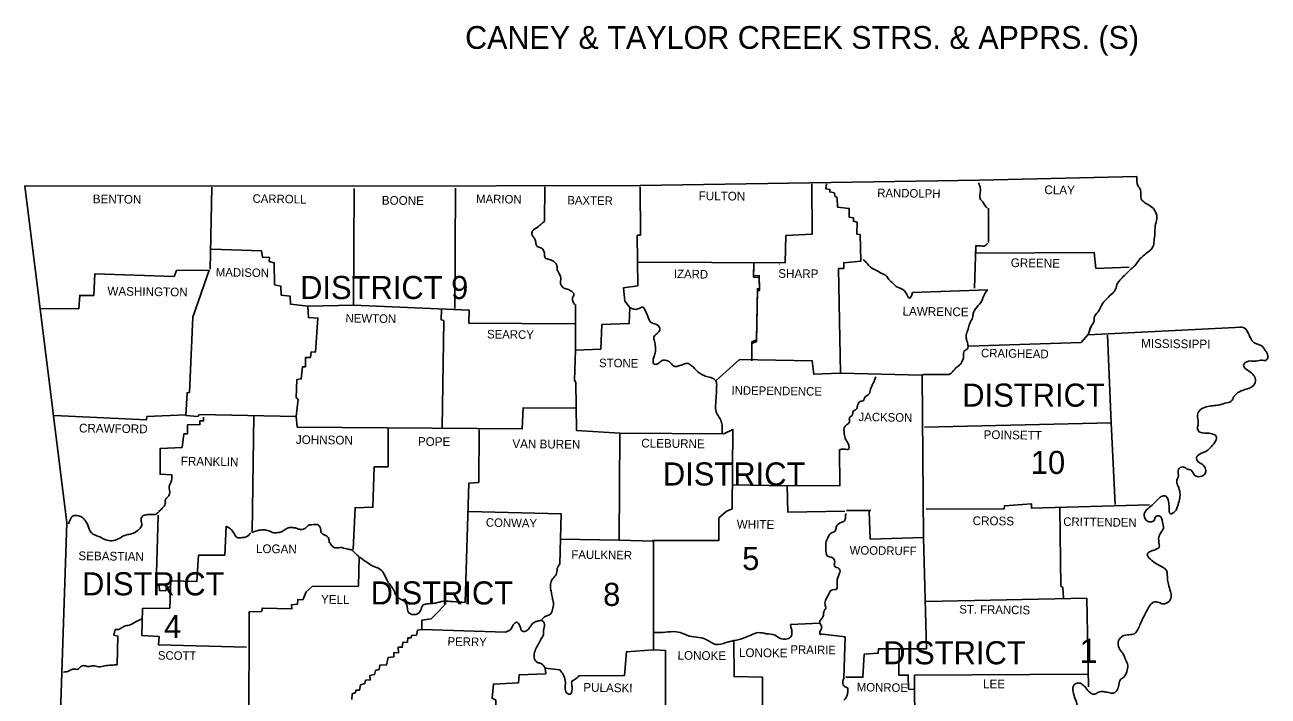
# Model space of a CAD drawing. Extents: x 172 to 3385, y 73 to 2074.
# Drawn here: x 2704 to 3304, y 1710 to 2034 of the extents above; entities that cross this region are included whole.
import ezdxf

# ---------------------------------------------------------------- set-up
doc = ezdxf.new("R2010")
doc.units = 0
for name, color, linetype in [('R_Border', 7, 'Continuous'), ('R_Border Prem', 7, 'Continuous'), ('R_Grid', 7, 'Continuous')]:
    doc.layers.add(name, color=color, linetype=linetype)

msp = doc.modelspace()

# ---------------------------------------------------------------- linework, layer by layer
at = {"layer": 'R_Border Prem'}
for p, q in [((3216.98, 1884.51), (3218.15, 1888.13)), ((3217.27, 1885.68), (3218.45, 1888.52)), ((3100.35, 1799.78), (3112, 1799.78))]:
    msp.add_line(p, q, dxfattribs=at)
for points in [[(2703.71, 1956.42), (2861.92, 1956.32), (3000.75, 1956.61), (3164.54, 1959.16), (3240.46, 1960.92)], [(3083.62, 1957.49), (3083.82, 1933.23), (3071.1, 1932.55), (3070.71, 1919.24), (2999.97, 1919.63)], [(3090.67, 1957.4), (3090.37, 1955.05), (3092.33, 1954.76), (3092.23, 1953.58), (3094.48, 1953.09), (3094.68, 1951.53), (3095.75, 1950.84), (3096.05, 1946.15), (3101.63, 1945.56), (3101.63, 1941.35), (3103.68, 1941.06), (3103.68, 1939.39), (3105.44, 1938.9), (3105.34, 1933.23), (3106.91, 1932.94), (3107.3, 1920.12), (3098.98, 1919.34), (3099.08, 1916.6), (3096.54, 1916.5), (3097.42, 1866.01), (3136.85, 1865.13), (3137.53, 1786.66), (3111.8, 1785.98), (3111.31, 1799.19)], [(2703.71, 1956.42), (2723.96, 1793.81), (2715.15, 1528.37)], [(2794.01, 1955.83), (2793.13, 1916.21)], [(2793.82, 1925.89), (2817.89, 1925.11), (2818.47, 1921.98), (2821.8, 1921.88), (2821.7, 1919.92), (2824.05, 1919.34), (2824.25, 1908.67), (2827.28, 1907.99), (2827.48, 1903.78), (2831.78, 1903.19), (2831.98, 1899.28), (2840.49, 1898.4), (2862.4, 1898.89), (2862.6, 1955.15)], [(2911.62, 1955.34), (2911.33, 1897.22)], [(2954.67, 1956.03), (2954.47, 1939.3)], [(3000.75, 1956.03), (3000.95, 1932.74), (2999.28, 1932.64), (2999.58, 1908.28), (2992.73, 1907.3), (2993.32, 1900.75), (2995.66, 1897.71), (2995.47, 1889.98), (2982.16, 1889.5), (2981.67, 1877.56), (2969.54, 1877.17), (2968.95, 1862.69), (2969.64, 1861.51), (2969.93, 1838.42), (2990.87, 1837.05), (2990.58, 1785.49), (3007.21, 1785), (3007.21, 1732.56), (2994.1, 1731.58), (2993.12, 1720.04), (2971.11, 1719.94)], [(3168.84, 1945.66), (3168.84, 1929.12)], [(3162.19, 1907.11), (3162.68, 1927.56), (3162.68, 1923.94), (3219.91, 1924.23), (3220.7, 1916.6), (3236.84, 1917.18)], [(2711.44, 1897.22), (2729.73, 1897.13), (2730.22, 1903.58), (2736.97, 1903.58), (2737.56, 1914.05), (2775.72, 1912.68), (2776.89, 1915.62), (2792.64, 1915.72), (2784.72, 1893.02), (2783.15, 1856.72), (2781.98, 1856.62), (2781.39, 1845.66), (2787.17, 1845.17), (2788.05, 1846.05), (2834.72, 1845.17), (2835.21, 1839.99)], [(3055.64, 1918.95), (3055.44, 1913.27), (3058.18, 1913.07), (3058.28, 1906.81), (3057.3, 1906.81), (3056.91, 1882.16), (3054.66, 1881.18), (3054.66, 1872.96)], [(3055.64, 1918.06), (3055.44, 1912.39), (3058.18, 1912.19), (3058.28, 1905.93), (3057.3, 1905.93), (3056.91, 1881.28), (3054.66, 1880.3), (3054.66, 1872.08)], [(3067.87, 1918.75), (3067.97, 1918.85)], [(3132.25, 1904.95), (3168.55, 1906.23)], [(2840.29, 1898.2), (2840.68, 1892.92), (2845.18, 1892.63), (2844.01, 1876.19), (2841.96, 1876.29), (2841.56, 1873.65), (2839.22, 1873.65), (2839.12, 1869.14), (2837.65, 1869.05), (2837.16, 1863.27), (2835.01, 1862.98), (2834.72, 1854.17), (2835.69, 1853.49), (2834.72, 1845.17)], [(2862.4, 1898.89), (2918.17, 1896.54), (2918.08, 1890.18), (2969.25, 1889.79)], [(2904.77, 1896.83), (2904.67, 1891.75), (2905.94, 1891.45), (2905.16, 1839.79)], [(2969.54, 1877.17), (2969.44, 1899.18)], [(3159.25, 1879.12), (3213.55, 1880.89), (3216.78, 1884.6)], [(3216.98, 1884.51), (3291.24, 1888.32)], [(3226.37, 1884.41), (3228.04, 1842.04), (3229.99, 1802.61)], [(3037.44, 1862.49), (3048.6, 1872.57), (3083.82, 1872.08), (3084.5, 1865.52), (3097.32, 1866.01)], [(3149.67, 1865.33), (3137.73, 1865.33), (3136.85, 1865.13)], [(2835.21, 1839.99), (2943.81, 1839.11), (2944.3, 1849.38), (2969.54, 1849.09)], [(2969.25, 1849.19), (2969.54, 1849.48)], [(2717.89, 1845.56), (2762.41, 1843.51), (2762.61, 1845.08), (2781.2, 1845.96)], [(2790, 1844.78), (2790, 1843.02), (2788.14, 1843.02), (2788.24, 1841.26), (2782.27, 1841.16), (2782.18, 1836.76), (2780.51, 1836.76), (2779.63, 1830.2), (2769.06, 1829.71), (2768.97, 1817.29), (2774.64, 1816.9)], [(2814.17, 1845.56), (2813.48, 1789.11)], [(2879.14, 1839.21), (2879.04, 1820.91), (2872.29, 1820.81), (2871.7, 1801.34), (2863.09, 1801.05), (2862.11, 1780.89)], [(2922.97, 1838.72), (2922.77, 1813.28), (2918.08, 1812.89), (2916.22, 1755.36)], [(2990.87, 1837.05), (3041.16, 1836.76), (3045.46, 1838.81), (3045.17, 1800.56), (3042.24, 1799.29), (3039.59, 1797.04), (3038.71, 1796.16), (3038.62, 1785.2), (3006.62, 1785.2)], [(3228.04, 1842.04), (3137.92, 1839.99)], [(3096.93, 1829.03), (3097.12, 1811.81), (3071.69, 1811.71), (3045.56, 1812.2)], [(3071.69, 1811.71), (3072.08, 1798.89), (3099.57, 1799.38)], [(3138.71, 1800.36), (3176.47, 1800.56), (3176.57, 1801.93), (3189.68, 1802.91), (3189.68, 1800.85), (3246.63, 1802.42)], [(3203.38, 1800.85), (3203.87, 1763.18), (3204.75, 1762.6), (3205.04, 1757.51)], [(2767.99, 1797.53), (2767.01, 1763.87), (2768.48, 1763.48), (2768.77, 1761.13), (2771.71, 1760.93), (2772, 1762.6), (2774.35, 1762.99)], [(2917.88, 1799.29), (2962.59, 1798.21), (2962.01, 1774.04)], [(3100.35, 1798.11), (3099.86, 1798.01)], [(2800.86, 1792.24), (2800.18, 1778.25), (2787.46, 1778.15), (2786.77, 1765.43), (2774.15, 1765.73), (2773.76, 1752.62), (2760.55, 1752.52), (2760.16, 1739.41), (2768.48, 1738.92), (2768.18, 1734.91), (2810.65, 1733.73)], [(2962.1, 1785.88), (2990.58, 1785.49)], [(3137.53, 1786.66), (3139, 1733.05), (3115.71, 1732.95), (3115.62, 1730.8), (3108.87, 1730.41), (3108.28, 1719.25), (3100.06, 1719.25)], [(2865.14, 1777.27), (2864.75, 1763.18), (2842.45, 1763.09), (2839.51, 1760.54), (2837.85, 1756.63), (2835.4, 1756.82), (2835.3, 1754.57), (2832.47, 1754.28), (2832.56, 1752.22), (2818.38, 1752.62), (2817.89, 1751.05), (2812.02, 1750.86), (2811.82, 1693.62)], [(2907.12, 1754.96), (2903.6, 1751.15), (2899.78, 1747.53), (2895.38, 1746.84), (2895.38, 1742.25), (2893.22, 1741.95), (2892.83, 1739.6), (2890.39, 1739.41), (2890.19, 1738.33), (2888.53, 1738.23), (2888.43, 1736.18), (2886.08, 1736.08), (2885.89, 1733.73), (2883.93, 1733.73), (2884.03, 1730.99), (2881.88, 1731.19), (2881.78, 1729.04), (2879.14, 1728.84), (2878.35, 1725.32), (2875.03, 1725.03), (2874.73, 1723.07), (2872.97, 1722.58), (2872.48, 1720.52), (2870.23, 1720.04), (2870.43, 1717.98), (2868.18, 1717.78), (2867.79, 1716.22), (2865.73, 1715.63), (2865.24, 1712.99), (2863.68, 1713.09), (2863.19, 1711.72), (2861.72, 1711.23), (2861.62, 1708.59)], [(3138.71, 1755.85), (3216.39, 1757.41)], [(3216.39, 1757.41), (3217.18, 1714.56)], [(2748.32, 1725.22), (2748.62, 1739.02), (2746.66, 1739.6), (2747.25, 1742.25)], [(2935.79, 1741.07), (2895.47, 1742.34)], [(3073.25, 1744.69), (3087.44, 1745.38)], [(3045.86, 1737.06), (3046.05, 1719.55), (3059.85, 1719.25), (3059.95, 1681.68)], [(3087.44, 1740.29), (3099.67, 1738.72), (3098.98, 1718.76)], [(3007.21, 1732.56), (3012.88, 1732.17), (3012.98, 1694.79), (3007.89, 1673.56), (3018.75, 1673.07), (3018.66, 1655.07)], [(3125.69, 1732.46), (3125.6, 1720.33), (3130.1, 1720.33), (3130.29, 1713.58), (3133.13, 1713.28)], [(2961.91, 1722.77), (2954.86, 1723.56), (2955.16, 1720.92), (2942.34, 1720.43), (2941.95, 1716.61), (2929.91, 1715.93), (2929.23, 1709.08), (2930.99, 1708.2), (2930.99, 1703.7)], [(2992.63, 1720.13), (2993.12, 1720.62)], [(3138.71, 1633.54), (3146.34, 1634.03), (3146.24, 1653.9), (3139.1, 1654.38), (3139.49, 1693.23), (3133.33, 1694.11), (3133.13, 1720.23), (3216.59, 1720.82)]]:
    msp.add_lwpolyline(points, dxfattribs=at)
for points in [[(3164.05, 1957.89), (3164.93, 1955.44), (3164.83, 1952.8), (3164.83, 1950.35), (3166.1, 1948.69), (3167.37, 1946.63), (3168.35, 1945.75)], [(3240.46, 1960.92), (3240.95, 1956.61), (3242.32, 1954.36), (3242.52, 1950.25), (3244.18, 1948.49), (3247.02, 1946.73), (3249.56, 1943.89), (3250.15, 1940.57), (3249.36, 1937.14), (3249.17, 1933.33), (3248.78, 1930), (3248.19, 1926.97), (3245.84, 1924.52), (3243.59, 1922.76), (3241.54, 1920.71), (3240.07, 1918.55), (3237.53, 1916.21), (3234.98, 1913.76), (3232.93, 1911.61), (3230.87, 1908.87), (3229.89, 1905.83), (3227.64, 1903.68), (3225.88, 1901.73), (3223.53, 1899.08), (3222.36, 1896.44), (3220.11, 1893.41), (3219.62, 1890.47), (3218.15, 1888.13), (3218.06, 1887.73)], [(2954.47, 1939.3), (2952.71, 1937.83), (2951.15, 1936.46), (2948.8, 1934.8), (2948.5, 1933.23), (2949.29, 1931.66), (2950.07, 1930.39), (2950.36, 1928.63), (2951.05, 1927.16), (2952.71, 1926.58), (2954.08, 1925.31), (2954.57, 1923.54), (2954.77, 1921.88), (2956.33, 1921.1), (2958.09, 1920.51), (2959.76, 1919.34), (2960.54, 1917.87), (2960.73, 1916.01), (2961.42, 1914.54), (2962.2, 1912.78), (2962.4, 1911.31), (2962.2, 1909.85), (2962.59, 1908.48), (2963.87, 1907.11), (2966.12, 1906.42), (2967.68, 1905.44), (2968.76, 1904.07), (2968.07, 1902.41), (2968.17, 1900.94), (2969.05, 1899.18)], [(3168.45, 1928.83), (3167.18, 1927.56), (3164.73, 1927.56), (3162.68, 1927.56)], [(3108.38, 1921), (3110.53, 1918.75), (3112.39, 1916.89), (3114.54, 1915.81), (3117.08, 1914.35), (3119.33, 1913.17), (3120.8, 1911.31), (3122.86, 1909.26), (3124.91, 1907.6), (3128.14, 1906.03), (3129.22, 1904.37), (3130.68, 1902.31), (3132.25, 1904.95)], [(3168.25, 1906.13), (3166.79, 1903.78), (3165.61, 1901.04), (3163.26, 1897.91), (3161.5, 1894.88), (3161.21, 1892.82), (3159.84, 1890.08), (3159.06, 1887.34), (3158.18, 1884.99), (3158.18, 1882.55), (3158.86, 1880.1), (3158.67, 1877.85), (3157.2, 1876.78), (3156.81, 1873.94), (3156.22, 1871.98), (3154.95, 1870.03), (3153.09, 1868.56), (3151.13, 1866.31), (3149.67, 1865.33)], [(2995.66, 1897.71), (2999.58, 1897.03), (3001.93, 1897.91), (3003.59, 1895.37), (3004.47, 1893.41), (3005.94, 1890.57), (3008.29, 1889.69), (3010.05, 1888.13), (3010.05, 1886.46), (3008.48, 1884.9), (3007.31, 1883.33), (3007.7, 1881.47), (3008.09, 1878.93), (3008.09, 1876.48), (3007.5, 1874.23), (3007.01, 1872.18), (3007.5, 1870.42), (3009.36, 1870.71), (3011.32, 1872.18), (3013.37, 1872.18), (3015.33, 1871.1), (3017.38, 1869.24), (3019.44, 1869.63), (3021.1, 1870.12), (3023.45, 1870.81), (3025.11, 1869.93), (3026.58, 1868.75), (3028.34, 1866.89), (3030.01, 1865.72), (3032.16, 1864.64), (3034.8, 1863.96), (3037.25, 1862.3), (3037.64, 1859.46), (3037.54, 1857.01), (3037.34, 1853.98), (3037.15, 1850.65), (3037.44, 1847.42), (3038.52, 1845.27), (3039.89, 1842.73), (3040.28, 1840.38), (3040.18, 1836.66)], [(3290.16, 1888.22), (3291.24, 1888.32), (3294.57, 1884.8), (3296.03, 1881.86), (3298.19, 1880.2), (3300.63, 1879.32), (3302.49, 1877.07), (3303.76, 1874.62), (3303.08, 1872.47), (3300.34, 1872.28), (3297.31, 1871.79), (3294.37, 1871.88), (3292.02, 1869.93), (3294.18, 1867.29), (3297.01, 1864.84), (3297.8, 1862.2), (3296.23, 1859.65), (3293.1, 1858.28), (3290.07, 1857.11), (3287.33, 1854.76), (3286.05, 1852.51), (3283.02, 1851.53), (3279.89, 1850.65), (3277.15, 1850.36), (3274.02, 1849.77), (3270.99, 1848.3), (3269.72, 1845.76), (3270.11, 1842.14), (3270.01, 1838.32), (3273.24, 1837.05), (3276.08, 1836.95), (3278.81, 1835.49), (3278.52, 1833.33), (3276.47, 1830.6), (3274.02, 1828.44), (3271.57, 1827.37), (3269.32, 1825.31), (3270.11, 1823.26), (3272.16, 1821.89), (3273.63, 1819.64), (3273.43, 1817.58), (3271.09, 1816.11), (3268.54, 1816.7), (3266.68, 1819.15), (3264.53, 1819.93), (3262.67, 1820.81), (3260.52, 1819.54), (3260.52, 1816.7), (3259.74, 1813.67), (3260.42, 1811.42), (3261.3, 1808.29), (3261.2, 1805.94), (3260.42, 1802.61), (3258.76, 1799.19), (3256.8, 1798.11), (3256.02, 1801.83), (3255.63, 1804.86), (3254.45, 1806.62), (3252.89, 1806.72), (3250.83, 1805.25), (3248.58, 1803), (3245.74, 1800.56), (3244.08, 1798.11), (3244.96, 1795.08), (3247.11, 1794.3), (3248.78, 1794.88), (3249.66, 1796.84), (3251.32, 1797.13), (3252.89, 1794.1)], [(3114.44, 1864.25), (3113.27, 1861.22), (3111.9, 1858.28), (3111.02, 1855.74), (3109.16, 1854.27), (3108.57, 1852.9), (3106.91, 1852.32), (3105.64, 1850.36), (3105.05, 1848.6), (3103.68, 1847.82), (3103, 1845.66), (3101.72, 1844.49), (3101.82, 1842.53), (3100.35, 1841.16), (3099.18, 1839.6), (3099.18, 1837.44), (3099.67, 1834.61), (3100.65, 1832.94), (3101.53, 1830.79), (3101.43, 1829.42), (3098.98, 1829.42), (3096.93, 1829.03)], [(2774.64, 1816.9), (2774.64, 1814.84), (2773.86, 1812.69), (2773.37, 1810.83), (2773.66, 1808.39), (2772.78, 1806.43), (2771.51, 1804.86), (2771.51, 1802.91), (2770.04, 1800.85), (2768.48, 1799.29), (2767.11, 1798.01), (2764.66, 1797.82), (2762.61, 1797.72), (2760.55, 1797.04), (2759.77, 1795.57), (2760.16, 1793.32), (2759.38, 1791.17), (2757.32, 1789.5), (2755.07, 1788.43), (2752.73, 1788.03), (2749.5, 1786.47), (2746.56, 1785.2), (2743.43, 1785.39), (2740.5, 1786.66), (2737.85, 1787.84), (2735.8, 1789.01), (2734.14, 1792.63), (2733.06, 1794.59), (2731.2, 1796.55), (2728.95, 1797.33), (2727.09, 1797.13), (2724.84, 1793.32)], [(3099.86, 1798.01), (3099.37, 1794.79), (3097.52, 1793.91), (3095.36, 1791.75), (3094.87, 1789.8), (3093.11, 1789.01), (3091.45, 1786.96), (3090.37, 1784.12), (3090.37, 1781.19), (3091.06, 1777.86), (3093.5, 1776.98), (3094.68, 1775.02), (3094.48, 1772.97), (3096.83, 1771.6), (3097.22, 1770.42), (3096.83, 1769.15), (3095.75, 1765.53), (3095.85, 1763.09), (3095.66, 1762.01), (3093.02, 1761.32), (3091.45, 1758.68), (3090.37, 1756.82), (3089.98, 1754.38), (3090.28, 1752.62), (3089.49, 1751.25), (3089.2, 1749.19), (3088.22, 1747.43), (3087.34, 1745.77), (3088.32, 1743.81), (3088.03, 1742.44), (3087.44, 1740.29), (3087.93, 1739.6)], [(2800.86, 1792.24), (2803.02, 1790.87), (2804.68, 1788.62), (2806.15, 1786.76), (2808.59, 1786.66), (2810.55, 1787.06), (2812.8, 1789.01)], [(2813.48, 1789.11), (2816.71, 1790.19), (2819.06, 1790.38), (2821.41, 1789.99), (2823.86, 1789.01), (2826.5, 1789.21), (2828.45, 1789.89), (2830.41, 1791.17), (2832.56, 1791.56), (2834.62, 1791.17), (2836.77, 1790.58), (2839.12, 1791.26), (2840.49, 1792.54), (2842.84, 1792.93), (2844.89, 1792.93), (2846.36, 1791.26), (2846.65, 1789.5), (2848.51, 1787.84), (2850.17, 1786.76), (2850.66, 1784.71), (2851.54, 1783.24), (2852.43, 1782.26), (2853.7, 1781.67), (2855.85, 1781.87), (2859.18, 1781.19), (2861.33, 1780.7), (2863.29, 1779.03), (2865.14, 1777.27)], [(3252.89, 1794.1), (3253.28, 1791.26), (3251.62, 1788.23), (3251.03, 1785.2), (3251.32, 1782.16), (3248.19, 1780.5), (3245.45, 1778.54), (3247.02, 1776.2), (3249.95, 1774.04), (3252.89, 1772.38), (3254.75, 1770.72), (3255.24, 1766.71), (3255.72, 1764.16), (3256.7, 1760.64), (3257.09, 1758.19), (3255.33, 1755.26), (3253.28, 1754.67), (3251.13, 1755.36), (3248.58, 1755.55), (3246.53, 1753.59), (3245.06, 1750.86), (3243.59, 1748.12), (3242.52, 1745.77), (3241.44, 1743.22), (3239.29, 1740.29), (3236.65, 1739.8), (3233.51, 1739.02), (3231.66, 1736.86), (3231.95, 1733.24), (3233.71, 1730.8), (3235.08, 1727.76), (3236.06, 1725.12), (3235.57, 1721.8), (3234.2, 1719.35), (3232.44, 1717.88), (3231.66, 1714.75), (3230.38, 1712.4), (3229.21, 1711.62), (3226.86, 1711.82), (3224.32, 1712.31), (3222.16, 1712.11), (3220.11, 1711.03), (3218.06, 1711.72), (3215.9, 1714.07), (3214.14, 1715.83), (3212.19, 1716.51), (3210.13, 1715.44), (3209.74, 1712.21), (3210.72, 1708.88), (3211.6, 1704.38), (3210.72, 1701.64), (3210.42, 1697.14)], [(2865.14, 1777.27), (2868.57, 1774.92), (2871.8, 1772.87), (2875.12, 1771.4), (2876.98, 1769.25), (2878.65, 1765.92), (2880.02, 1763.87), (2881.78, 1761.32), (2883.05, 1758.49), (2885.1, 1756.92), (2887.26, 1755.55), (2888.33, 1753.11), (2888.82, 1750.66), (2891.17, 1749.49), (2893.42, 1749.97), (2894.69, 1751.44), (2895.87, 1753.99), (2898.51, 1754.77), (2901.93, 1755.06), (2905.85, 1755.94), (2910.15, 1755.75), (2916.22, 1755.36)], [(2962.01, 1774.04), (2960.73, 1771.79), (2960.15, 1768.86), (2958.58, 1767), (2957.6, 1764.85), (2957.51, 1762.01), (2958, 1759.47), (2958.48, 1757.02), (2958.88, 1754.77), (2958.39, 1751.93), (2957.11, 1749.49), (2955.16, 1748.8), (2953.3, 1747.14)], [(2747.25, 1742.25), (2749.4, 1742.44), (2751.45, 1743.81), (2754.19, 1744.4), (2756.93, 1745.87), (2760.36, 1747.43)], [(2935.79, 1741.07), (2938.23, 1742.44), (2939.5, 1744.5), (2941.07, 1745.77), (2942.63, 1744.01), (2944, 1741.46), (2945.47, 1741.46), (2947.33, 1743.22), (2948.5, 1744.79), (2949.97, 1745.96), (2951.54, 1746.45), (2953.2, 1746.65), (2954.47, 1744.79), (2954.08, 1741.85), (2954.08, 1739.9), (2953.01, 1737.84), (2951.83, 1735.69), (2950.56, 1733.24), (2949.58, 1730.6), (2949.78, 1728.06), (2951.15, 1726.39), (2952.71, 1725.91), (2954.86, 1723.75)], [(3007.4, 1740.78), (3012.88, 1740.97), (3018.26, 1741.17), (3021.69, 1740.19), (3025.6, 1738.92), (3030.2, 1738.33), (3033.43, 1737.06), (3037.25, 1735.1), (3042.14, 1735.98), (3045.95, 1736.96), (3050.94, 1738.23), (3054.17, 1739.6), (3057.89, 1740.78), (3061.61, 1740.29), (3065.82, 1739.51), (3068.46, 1737.94), (3073.25, 1738.63), (3073.25, 1744.69)], [(2748.32, 1725.22), (2745.49, 1725.12), (2742.26, 1724.73), (2739.32, 1724.34), (2736.68, 1724.83), (2734.23, 1724.44), (2732.57, 1724.83), (2730.52, 1724.34), (2729.34, 1723.17), (2726.9, 1723.17), (2725.13, 1722.38), (2722.3, 1721.7)], [(2961.91, 1722.77), (2963.57, 1720.62), (2964.55, 1717.69), (2964.55, 1714.36), (2965.33, 1711.62), (2966.9, 1711.03), (2967.88, 1713.38), (2967.68, 1715.73), (2967.68, 1717.1), (2969.34, 1718.27), (2971.11, 1719.94)], [(3098.98, 1718.76), (3098.59, 1716.81), (3099.37, 1714.75), (3100.74, 1714.07), (3100.94, 1712.11), (3100.45, 1710.15), (3100.06, 1709.37), (3099.18, 1708.2)]]:
    msp.add_spline(points, degree=3, dxfattribs=at)

# ---------------------------------------------------------------- texts
at = {"layer": 'R_Border'}
msp.add_text('CANEY & TAYLOR CREEK STRS. & APPRS. (S)', height=11, dxfattribs=at).set_placement((2916.23, 2022.61))
for s, height, rotation, p in [('CLAY', 4.206, 359.22578, (3195.85, 1952.5)), ('BENTON', 4.207, 359.25271, (2736.48, 1948.1)), ('CARROLL', 4.109, 359.14808, (2813.58, 1948.3)), ('BOONE', 4.207, 359.40007, (2876, 1947.42)), ('MARION', 4.109, 359.18542, (2921.5, 1948.2)), ('BAXTER', 4.109, 359.25594, (2965.53, 1947.51)), ('FULTON', 4.206, 359.49961, (3028.93, 1949.57)), ('RANDOLPH', 4.109, 359.25835, (3115.13, 1951.04)), ('GREENE', 4.207, 359.2361, (3179.6, 1917.28)), ('MADISON', 4.109, 359.09062, (2795.87, 1912.78)), ('IZARD', 4.108, 358.92583, (3016.99, 1912)), ('SHARP', 4.206, 359.39049, (3067.38, 1912.1)), ('WASHINGTON', 4.206, 359.23201, (2743.53, 1903.58)), ('LAWRENCE', 4.207, 359.26783, (3127.36, 1893.9)), ('NEWTON', 4.109, 359.2717, (2858.49, 1890.57)), ('SEARCY', 4.108, 359.25271, (2926.78, 1882.84)), ('MISSISSIPPI', 4.2062, 359.30972, (3242.52, 1878.34)), ('STONE', 4.108, 359.40007, (2980.89, 1868.95)), ('CRAIGHEAD', 4.109, 359.11587, (3165.22, 1873.74)), ('INDEPENDENCE', 4.1081, 359.21874, (3044.78, 1855.74)), ('JACKSON', 4.108, 359.13523, (3106.13, 1842.92)), ('CRAWFORD', 4.206, 359.27706, (2729.83, 1837.44)), ('POINSETT', 4.206, 359.19871, (3166.49, 1834.31)), ('JOHNSON', 4.207, 359.3514, (2834.52, 1831.87)), ('POPE', 4.207, 359.61547, (2893.42, 1830.99)), ('VAN BUREN', 4.207, 359.35078, (2939.01, 1829.91)), ('CLEBURNE', 4.206, 359.25352, (3001.24, 1830.2)), ('FRANKLIN', 4.207, 359.18154, (2778.95, 1821.5)), ('CONWAY', 4.108, 359.03714, (2926.2, 1791.95)), ('WHITE', 4.207, 359.31386, (3047.32, 1791.07)), ('CROSS', 4.206, 359.38394, (3161.21, 1792.73)), ('CRITTENDEN', 4.109, 359.21302, (3204.94, 1792.34)), ('LOGAN', 4.207, 359.39691, (2815.25, 1779.23)), ('WOODRUFF', 4.108, 359.27478, (3101.82, 1778.54)), ('SEBASTIAN', 4.206, 359.28159, (2729.54, 1775.8)), ('FAULKNER', 4.109, 359.24862, (2967.49, 1776.49)), ('YELL', 4.207, 359.19871, (2846.65, 1754.77)), ('ST. FRANCIS', 4.1081, 359.22157, (3154.75, 1750.07)), ('PERRY', 4.109, 359.08578, (2907.71, 1734.52)), ('PRAIRIE', 4.109, 359.21158, (3073.25, 1730.6)), ('SCOTT', 4.109, 359.40628, (2767.89, 1727.76)), ('LONOKE', 4.207, 359.49742, (3018.75, 1727.76)), ('LONOKE', 4.207, 359.49742, (3048.4, 1729.04)), ('PULASKI', 4.207, 359.05305, (2973.26, 1712.31)), ('MONROE', 4.108, 359.03308, (3105.25, 1712.5)), ('LEE', 4.207, 359.43273, (3166.2, 1713.97))]:
    msp.add_text(s, height=height, rotation=rotation, dxfattribs=at).set_placement(p)
at = {"layer": 'R_Border Prem'}
msp.add_text('1', height=11.74, dxfattribs=at).set_placement((3212.77, 1726.2))
at = {"layer": 'R_Grid'}
for s, height, p in [('DISTRICT 9', 11.154, (2836.57, 1901.82)), ('DISTRICT', 11.154, (3156.22, 1849.87)), ('10', 11.154, (3189.29, 1817.39)), ('DISTRICT', 11.154, (3011.71, 1811.81)), ('5', 11.15, (3049.97, 1771.01)), ('DISTRICT', 11.154, (2731.3, 1758.78)), ('DISTRICT', 11.154, (2870.62, 1754.38)), ('8', 11.15, (2982.85, 1753.69)), ('4', 11.15, (2770.92, 1738.23)), ('DISTRICT', 11.154, (3118.06, 1725.51))]:
    msp.add_text(s, height=height, dxfattribs=at).set_placement(p)

doc.saveas('drawing.dxf')
